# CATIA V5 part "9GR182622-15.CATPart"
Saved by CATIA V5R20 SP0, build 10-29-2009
Part number: 9GR182622-15
Revision: ANY
Definition: UNKNOWN
Nomenclature: 9GR182622-15
Source: Unknown
Bounding box of the stored display mesh (mm): x -10.897 to 10.833, y -21 to 5, z -11 to 11
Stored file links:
  C:\Users\Utente\Desktop\IO LAVORO\3D X SITO CF\CUMSA\3D files GR\GR 182622-15\9GR182622-15.CATPart
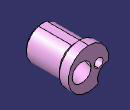
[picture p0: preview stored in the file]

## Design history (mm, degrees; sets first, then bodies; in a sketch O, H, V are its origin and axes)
Body1 "Cortar-Extruir7" (main body)
  Solid1: solid without history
